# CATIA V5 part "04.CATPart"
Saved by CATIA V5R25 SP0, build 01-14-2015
Part number: Part2
Bounding box of the stored display mesh (mm): x -5 to 5, y -9.915 to 10, z -106.824 to 9.932
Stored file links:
  D:\feridun18052022montaj\04.CATPart
  D:\feridun18052022montaj\cektirme.CATProduct
  D:\feridun18052022montaj\03.CATPart
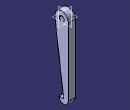
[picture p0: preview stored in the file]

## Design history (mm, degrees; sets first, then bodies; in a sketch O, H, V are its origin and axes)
Body1 (main body)
  Sketch1 on yz-plane, origin (0, 0, 0), H (0, 1, 0), V (0, 0, 1)
    arc A1 centre (0, 0) radius 10 from (10, 0) to (-9.9155, -1.2975) ccw
    point P1 (10, 0)
    line L1 (10, 0) -> (10, -100)
    arc A2 centre (3, -100) radius 7 from (10, -100) to (-4, -100) cw
    line L2 (-4, -100) -> (3, -100)
    point P5 (3, -100)
    line L3 (3, -100) -> (-9.9155, -1.2975)
    circle A3 centre (0, 0) radius 4
    radius A1 = 10
    distance P5 L1 = 7
    distance L2 H = 100
    radius A2 = 7
    length L1 = 100
    radius A3 = 4
    coincidence: P1 H
    tangency: L1 A1, A2 L1, L3 A1
    horizontal: L2 H
  Pad1: profile Sketch1, direction (1, 0, 0), length 5, mirrored extent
